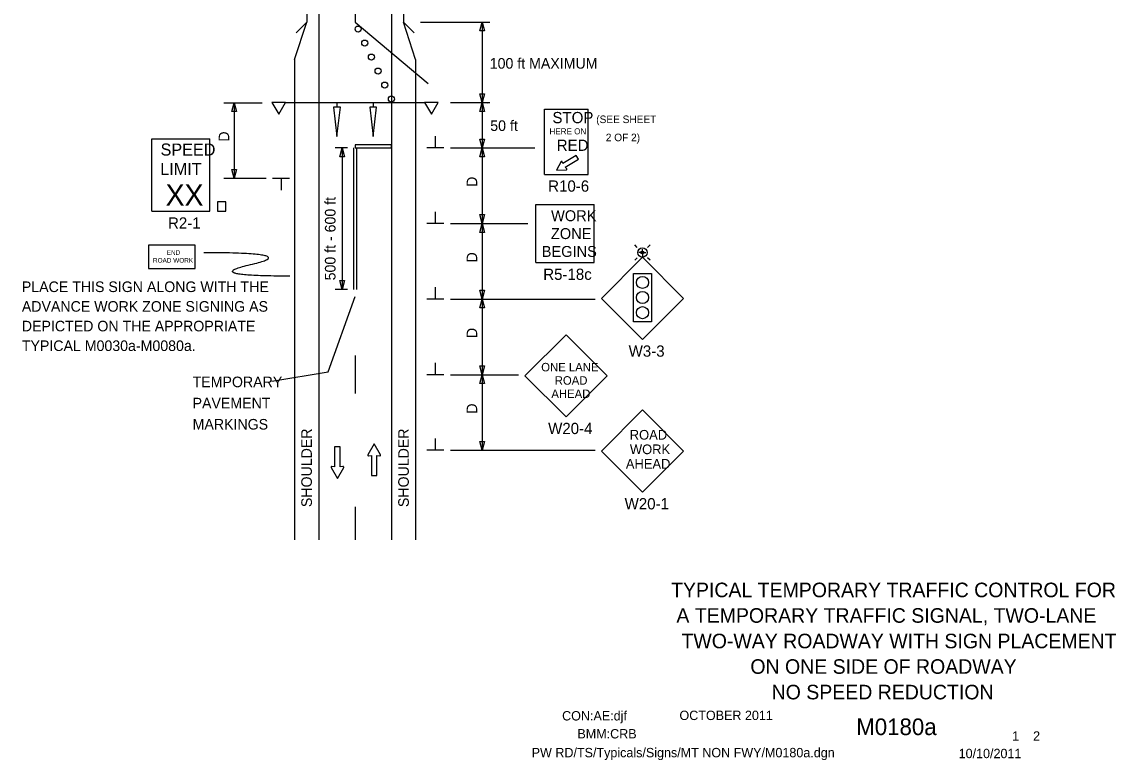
# Model space of a CAD drawing. Extents: x 16733 to 18484, y 7218 to 8208.
# Drawn here: x 16733 to 17457, y 7218 to 7706 of the extents above; entities that cross this region are included whole.
import ezdxf

# ---------------------------------------------------------------- set-up
doc = ezdxf.new("R2010")
doc.units = 0
for name, color, linetype in [('ALI_LEGAL_EX', 7, 'Continuous'), ('BORDER', 7, 'Continuous'), ('BORDER_SIGNAL_WO', 7, 'Continuous'), ('MT_SCRATCH_LEVEL_E', 7, 'Continuous'), ('PAVT_EDGE_EX', 7, 'Continuous'), ('TRAFFIC_SIGNS_PR', 7, 'Continuous'), ('TYPICAL_TEXT_DIMEN_PR', 7, 'Continuous')]:
    doc.layers.add(name, color=color, linetype=linetype)

msp = doc.modelspace()

# ---------------------------------------------------------------- linework, layer by layer
at = {"layer": 'ALI_LEGAL_EX'}
for points in [[(16952.78, 7623.01), (16952.78, 7529.38)], [(16954.78, 7623.01), (16954.78, 7529.38)], [(16953.78, 7485.68), (16953.78, 7460.68)], [(16953.78, 7385.68), (16953.78, 7363.75)]]:
    msp.add_lwpolyline(points, dxfattribs=at)
at = {"layer": 'BORDER'}
msp.add_line((17041.19, 7652.2), (17041.19, 7652.2), dxfattribs=at)
at = {"layer": 'MT_SCRATCH_LEVEL_E'}
for p, q in [((16943.98, 7425.26), (16940.24, 7425.26)), ((16940.24, 7425.26), (16940.24, 7412.01)), ((16943.98, 7425.26), (16940.24, 7425.26)), ((16940.24, 7425.26), (16940.24, 7412.01)), ((16943.98, 7412.01), (16943.98, 7425.26)), ((16943.98, 7412.01), (16943.98, 7425.26)), ((16966.37, 7427.22), (16962.26, 7419.98)), ((16966.37, 7427.22), (16962.26, 7419.98)), ((16970.52, 7419.98), (16966.37, 7427.22)), ((16970.52, 7419.98), (16966.37, 7427.22)), ((16962.74, 7419.29), (16964.52, 7419.61)), ((16962.74, 7419.29), (16964.52, 7419.61)), ((16964.52, 7419.61), (16964.52, 7406.35)), ((16964.52, 7419.61), (16964.52, 7406.35)), ((16968.26, 7406.35), (16968.26, 7419.61)), ((16968.26, 7419.61), (16970.04, 7419.29)), ((16968.26, 7406.35), (16968.26, 7419.61)), ((16968.26, 7419.61), (16970.04, 7419.29)), ((16937.98, 7411.64), (16942.13, 7404.4)), ((16937.98, 7411.64), (16942.13, 7404.4)), ((16940.24, 7412.01), (16938.46, 7412.32)), ((16940.24, 7412.01), (16938.46, 7412.32)), ((16942.13, 7404.4), (16946.24, 7411.64)), ((16942.13, 7404.4), (16946.24, 7411.64)), ((16945.76, 7412.32), (16943.98, 7412.01)), ((16945.76, 7412.32), (16943.98, 7412.01)), ((16964.52, 7406.35), (16968.26, 7406.35)), ((16964.52, 7406.35), (16968.26, 7406.35))]:
    msp.add_line(p, q, dxfattribs=at)
for centre, start, end in [((16962.67, 7419.75), 150.42484, 279.96381), ((16962.67, 7419.75), 150.42484, 279.96381), ((16970.11, 7419.75), 260.03619, 29.77312), ((16970.11, 7419.75), 260.03619, 29.77312), ((16938.39, 7411.86), 80.03619, 209.77312), ((16938.39, 7411.86), 80.03619, 209.77312), ((16945.83, 7411.86), 330.42484, 99.96381), ((16945.83, 7411.86), 330.42484, 99.96381)]:
    msp.add_arc(centre, 0.463, start, end, dxfattribs=at)
at = {"layer": 'PAVT_EDGE_EX'}
for p, q in [((16929.78, 8185.68), (16929.78, 7363.75)), ((16977.78, 8185.68), (16977.78, 7363.75)), ((16921.78, 7837.6), (16921.78, 7706.21)), ((16953.78, 7837.6), (16953.78, 7706.21)), ((16985.78, 7837.6), (16985.78, 7706.21)), ((16913.78, 7681.51), (16921.78, 7706.21)), ((16921.78, 7706.21), (16914.71, 7699.14)), ((16953.78, 7706.21), (17002.19, 7665.59)), ((16985.78, 7706.21), (16992.85, 7699.14)), ((16993.78, 7681.51), (16985.78, 7706.21)), ((16913.78, 7681.51), (16913.78, 7363.75)), ((16993.78, 7681.51), (16993.78, 7363.75))]:
    msp.add_line(p, q, dxfattribs=at)
at = {"layer": 'TRAFFIC_SIGNS_PR'}
for p, q in [((16907.78, 7653.01), (16999.78, 7653.01)), ((16941.78, 7653.01), (16941.78, 7649.99)), ((16965.78, 7653.01), (16965.78, 7649.99)), ((17079.1, 7648.69), (17107.9, 7648.69)), ((17079.1, 7605.49), (17079.1, 7648.69)), ((17093.5, 7648.69), (17093.5, 7648.69)), ((17107.9, 7605.49), (17107.9, 7648.69)), ((16819.37, 7629.06), (16857.77, 7629.06)), ((16819.37, 7581.06), (16819.37, 7629.06)), ((16857.77, 7581.06), (16857.77, 7629.06)), ((17079.1, 7605.49), (17107.9, 7605.49)), ((17073.38, 7547.16), (17073.38, 7585.56)), ((17073.38, 7585.56), (17111.78, 7585.56)), ((17111.78, 7547.16), (17111.78, 7585.56)), ((16819.37, 7581.06), (16857.77, 7581.06)), ((17140.4, 7557.23), (17138.77, 7558.86)), ((17143.82, 7553.8), (17143.82, 7556.11)), ((17147.24, 7557.23), (17148.87, 7558.86)), ((17143.82, 7550.65), (17116.67, 7523.5)), ((17140.4, 7550.38), (17138.77, 7548.75)), ((17143.82, 7553.8), (17141.52, 7553.8)), ((17143.82, 7553.8), (17143.82, 7550.65)), ((17143.82, 7553.8), (17146.12, 7553.8)), ((17170.97, 7523.5), (17143.82, 7550.65)), ((17148.87, 7548.75), (17147.24, 7550.38)), ((17073.38, 7547.16), (17111.78, 7547.16)), ((17116.67, 7523.5), (17143.82, 7496.35)), ((17143.82, 7496.35), (17170.97, 7523.5)), ((17093.27, 7499.48), (17066.12, 7472.33)), ((17120.43, 7472.33), (17093.27, 7499.48)), ((17066.12, 7472.33), (17093.27, 7445.18)), ((17093.27, 7445.18), (17120.43, 7472.33)), ((17143.86, 7449.68), (17116.71, 7422.53)), ((17171.02, 7422.53), (17143.86, 7449.68)), ((17116.71, 7422.53), (17143.86, 7395.37)), ((17143.86, 7395.37), (17171.02, 7422.53))]:
    msp.add_line(p, q, dxfattribs=at)
for points in [[(16898.78, 7653.01), (16903.28, 7645.22), (16907.78, 7653.01)], [(16939.53, 7649.99), (16941.78, 7630.57), (16944.03, 7649.99)], [(16963.53, 7649.99), (16965.78, 7630.57), (16968.03, 7649.99)], [(16999.78, 7653.01), (17004.28, 7645.22), (17008.78, 7653.01)], [(16953.78, 7625.01), (16953.78, 7623.01), (16977.78, 7623.01), (16977.78, 7625.01)], [(16862.78, 7581.06), (16868.38, 7581.06), (16868.38, 7587.23), (16862.78, 7587.23)], [(16817.21, 7543.32), (16847.93, 7543.32), (16847.93, 7558.68), (16817.21, 7558.68)], [(17149.88, 7508.04), (17137.88, 7508.04), (17137.88, 7540.04), (17149.88, 7540.04)]]:
    msp.add_lwpolyline(points, close=True, dxfattribs=at)
for points in [[(17090.11, 7613.94), (17087.06, 7608.3), (17093.45, 7608.55)], [(17093.7, 7609.14), (17092.78, 7610.17), (17101.44, 7615.53), (17099.92, 7617.97), (17091.27, 7612.61), (17090.75, 7613.9)]]:
    msp.add_lwpolyline(points, dxfattribs=at)
for centre, radius in [((16955.78, 7701.63), 2), ((16960.18, 7692.37), 2), ((16964.58, 7683.1), 2), ((16968.98, 7673.84), 2), ((16973.38, 7664.57), 2), ((16977.78, 7655.31), 2), ((17143.82, 7553.8), 3.15), ((17143.82, 7553.8), 1.02), ((17143.88, 7534.04), 4), ((17143.88, 7524.04), 4), ((17143.88, 7514.04), 4)]:
    msp.add_circle(centre, radius, dxfattribs=at)
for centre, radius, start, end in [((17090.42, 7613.77), 0.355, 21.71521, 151.42661), ((17093.44, 7608.9), 0.354, 272.17868, 41.91782)]:
    msp.add_arc(centre, radius, start, end, dxfattribs=at)
msp.add_open_spline([(16910.65, 7538.19), (16850.96, 7538.19), (16918.98, 7553.67), (16853.79, 7553.67)], degree=2, dxfattribs=at)
at = {"layer": 'TYPICAL_TEXT_DIMEN_PR'}
for p, q in [((16997.08, 7706.21), (17042.78, 7706.21)), ((17036.21, 7700.35), (17037.78, 7706.21)), ((17037.78, 7700.35), (17036.21, 7700.35)), ((17037.78, 7706.21), (17037.78, 7653.01)), ((17037.78, 7706.21), (17039.35, 7700.35)), ((17039.35, 7700.35), (17037.78, 7700.35)), ((17037.78, 7653.01), (17036.21, 7658.88)), ((17036.21, 7658.88), (17037.78, 7658.88)), ((17037.78, 7658.88), (17039.35, 7658.88)), ((17039.35, 7658.88), (17037.78, 7653.01)), ((16867.03, 7652.92), (16892.38, 7652.92)), ((16872.21, 7647.06), (16873.78, 7652.92)), ((16873.78, 7652.92), (16873.78, 7602.92)), ((16873.78, 7652.92), (16875.35, 7647.06)), ((17016.78, 7653.01), (17042.78, 7653.01)), ((17036.21, 7647.15), (17037.78, 7653.01)), ((17037.78, 7653.01), (17039.35, 7647.15)), ((17037.78, 7653.01), (17037.78, 7623.01)), ((16873.78, 7647.06), (16872.21, 7647.06)), ((16875.35, 7647.06), (16873.78, 7647.06)), ((17037.78, 7647.15), (17036.21, 7647.15)), ((17039.35, 7647.15), (17037.78, 7647.15)), ((17006.91, 7623.01), (17006.91, 7630.8)), ((17037.78, 7623.01), (17036.21, 7628.88)), ((17036.21, 7628.88), (17037.78, 7628.88)), ((17037.78, 7628.88), (17039.35, 7628.88)), ((17039.35, 7628.88), (17037.78, 7623.01)), ((16948.75, 7623.01), (16940.55, 7623.01)), ((16943.66, 7617.15), (16945.23, 7623.01)), ((16945.23, 7623.01), (16945.23, 7529.38)), ((16945.23, 7623.01), (16946.8, 7617.15)), ((17012.53, 7623.01), (17001.28, 7623.01)), ((17016.78, 7623.01), (17072.75, 7623.01)), ((17036.21, 7617.15), (17037.78, 7623.01)), ((17037.78, 7623.01), (17037.78, 7573.01)), ((17037.78, 7623.01), (17039.35, 7617.15)), ((16945.23, 7617.15), (16943.66, 7617.15)), ((16946.8, 7617.15), (16945.23, 7617.15)), ((17037.78, 7617.15), (17036.21, 7617.15)), ((17039.35, 7617.15), (17037.78, 7617.15)), ((16873.78, 7602.92), (16872.21, 7608.78)), ((16872.21, 7608.78), (16873.78, 7608.78)), ((16873.78, 7608.78), (16875.35, 7608.78)), ((16875.35, 7608.78), (16873.78, 7602.92)), ((16867.03, 7602.92), (16894.99, 7602.92)), ((16899.24, 7602.92), (16910.49, 7602.92)), ((16904.87, 7602.92), (16904.87, 7595.13)), ((17006.91, 7573.01), (17006.91, 7580.8)), ((17037.78, 7573.01), (17036.21, 7578.88)), ((17036.21, 7578.88), (17037.78, 7578.88)), ((17037.78, 7578.88), (17039.35, 7578.88)), ((17039.35, 7578.88), (17037.78, 7573.01)), ((17012.53, 7573.01), (17001.28, 7573.01)), ((17016.78, 7573.01), (17067.97, 7573.01)), ((17036.21, 7567.15), (17037.78, 7573.01)), ((17037.78, 7573.01), (17037.78, 7523.01)), ((17037.78, 7573.01), (17039.35, 7567.15)), ((17037.78, 7567.15), (17036.21, 7567.15)), ((17039.35, 7567.15), (17037.78, 7567.15)), ((16945.23, 7529.38), (16943.66, 7535.25)), ((16943.66, 7535.25), (16945.23, 7535.25)), ((16945.23, 7535.25), (16946.8, 7535.25)), ((16946.8, 7535.25), (16945.23, 7529.38)), ((16948.75, 7529.38), (16940.55, 7529.38)), ((17006.91, 7523.01), (17006.91, 7530.8)), ((17037.78, 7523.01), (17036.21, 7528.88)), ((17036.21, 7528.88), (17037.78, 7528.88)), ((17037.78, 7528.88), (17039.35, 7528.88)), ((17039.35, 7528.88), (17037.78, 7523.01)), ((16936.01, 7475.01), (16953.91, 7524.73)), ((17012.53, 7523.01), (17001.28, 7523.01)), ((17016.78, 7523.01), (17112.49, 7523.01)), ((17036.21, 7517.15), (17037.78, 7523.01)), ((17036.21, 7517.15), (17037.78, 7523.01)), ((17037.78, 7523.01), (17037.78, 7473.01)), ((17037.78, 7523.01), (17039.35, 7517.15)), ((17037.78, 7523.01), (17039.35, 7517.15)), ((17037.78, 7517.15), (17036.21, 7517.15)), ((17037.78, 7517.15), (17036.21, 7517.15)), ((17039.35, 7517.15), (17037.78, 7517.15)), ((17039.35, 7517.15), (17037.78, 7517.15)), ((17006.91, 7473.01), (17006.91, 7480.8)), ((17037.78, 7473.01), (17036.21, 7478.88)), ((17036.21, 7478.88), (17037.78, 7478.88)), ((17037.78, 7478.88), (17039.35, 7478.88)), ((17039.35, 7478.88), (17037.78, 7473.01)), ((16898.72, 7468.66), (16936.01, 7475.01)), ((17012.53, 7473.01), (17001.28, 7473.01)), ((17016.78, 7473.01), (17061.77, 7473.01)), ((17036.21, 7467.15), (17037.78, 7473.01)), ((17037.78, 7473.01), (17037.78, 7423.01)), ((17037.78, 7473.01), (17039.35, 7467.15)), ((17037.78, 7467.15), (17036.21, 7467.15)), ((17039.35, 7467.15), (17037.78, 7467.15)), ((17006.91, 7423.01), (17006.91, 7430.8)), ((17037.78, 7423.01), (17036.21, 7428.88)), ((17036.21, 7428.88), (17037.78, 7428.88)), ((17037.78, 7428.88), (17039.35, 7428.88)), ((17039.35, 7428.88), (17037.78, 7423.01)), ((17012.53, 7423.01), (17001.28, 7423.01)), ((17016.78, 7423.01), (17112.49, 7423.01))]:
    msp.add_line(p, q, dxfattribs=at)

# ---------------------------------------------------------------- texts
at = {"layer": 'BORDER'}
for s, p in [('TYPICAL TEMPORARY TRAFFIC CONTROL FOR', (17162.75, 7325.83)), ('A TEMPORARY TRAFFIC SIGNAL, TWO-LANE', (17166.27, 7308.94)), ('TWO-WAY ROADWAY WITH SIGN PLACEMENT', (17169.63, 7292.06)), ('ON ONE SIDE OF ROADWAY', (17215.2, 7275.17)), ('NO SPEED REDUCTION', (17229.25, 7258.28))]:
    msp.add_text(s, height=9.6347, dxfattribs=at).set_placement(p)
at = {"layer": 'BORDER_SIGNAL_WO'}
for s, height, p in [('CON:AE:djf', 6.2, (17090.69, 7244.31)), ('    OCTOBER 2011    ', 6.2, (17159.08, 7244.59)), ('    M0180a    ', 11, (17268.86, 7234.63)), ('BMM:CRB   ', 6.2, (17100.81, 7232.42)), (' 1    2 ', 6.2, (17386.05, 7230.95)), ('PW RD/TS/Typicals/Signs/MT NON FWY/M0180a.dgn     ', 6.2, (17070.55, 7219.96)), ('10/10/2011    ', 6.2, (17352.93, 7219.38))]:
    msp.add_text(s, height=height, dxfattribs=at).set_placement(p)
at = {"layer": 'TRAFFIC_SIGNS_PR'}
for s, height, p in [('STOP', 7.44, (17084.3, 7639.35)), ('HERE ON', 4, (17082.31, 7631.99)), ('RED', 7.44, (17087.11, 7621.04)), ('SPEED', 8, (16825.13, 7617.92)), ('LIMIT', 8, (16824.97, 7605.12)), ('XX', 14.031, (16828.48, 7584.82)), ('R10-6', 7.44, (17081.48, 7594.05)), ('R2-1', 7.44, (16830.04, 7569.62)), ('WORK', 7.217, (17083.38, 7574.53)), ('ZONE', 7.217, (17083.27, 7562.72)), ('END', 3.065, (16829.21, 7552.22)), ('BEGINS', 7.217, (17077.19, 7550.91)), ('ROAD WORK', 3.065, (16820.1, 7547.11)), ('R5-18c', 7.44, (17078.2, 7535.72)), ('PLACE THIS SIGN ALONG WITH THE', 7, (16733.39, 7527.67)), ('ADVANCE WORK ZONE SIGNING AS', 7, (16733.39, 7514.67)), ('DEPICTED ON THE APPROPRIATE', 7, (16733.39, 7501.67)), ('TYPICAL M0030a-M0080a.', 7, (16733.39, 7488.67)), ('W3-3', 7.44, (17134.69, 7484.91)), ('ONE LANE', 5.6, (17076.86, 7475.2)), ('ROAD', 5.6, (17085.81, 7466.4)), ('AHEAD', 5.6, (17083.57, 7457.6)), ('W20-4', 7.44, (17081.45, 7433.74)), ('ROAD', 6.4, (17135.41, 7430.06)), ('WORK', 6.4, (17135.52, 7420.46)), ('AHEAD', 6.4, (17132.83, 7410.86)), ('W20-1', 7.44, (17132.03, 7383.94))]:
    msp.add_text(s, height=height, dxfattribs=at).set_placement(p)
at = {"layer": 'TYPICAL_TEXT_DIMEN_PR'}
for s, height, p in [('100 ft MAXIMUM', 7, (17042.82, 7675.42)), ('(SEE SHEET', 5, (17113.25, 7639.42)), ('50 ft', 7, (17043.16, 7634.22)), ('2 OF 2)', 5, (17119.58, 7627.42)), ('TEMPORARY', 7, (16846.33, 7464.73)), ('PAVEMENT', 7, (16846.33, 7450.73)), ('MARKINGS', 7, (16846.33, 7436.73))]:
    msp.add_text(s, height=height, dxfattribs=at).set_placement(p)
for s, p in [('D', (16870.56, 7627.14)), ('D', (17034.56, 7597.23)), ('500 ft - 600 ft', (16940.83, 7535.4)), ('D', (17034.56, 7547.23)), ('D', (17034.56, 7497.23)), ('D', (17034.56, 7447.23)), ('SHOULDER', (16925.2, 7385.43)), ('SHOULDER', (16989.31, 7385.43))]:
    msp.add_text(s, height=7, rotation=90, dxfattribs=at).set_placement(p)

doc.saveas('drawing.dxf')
